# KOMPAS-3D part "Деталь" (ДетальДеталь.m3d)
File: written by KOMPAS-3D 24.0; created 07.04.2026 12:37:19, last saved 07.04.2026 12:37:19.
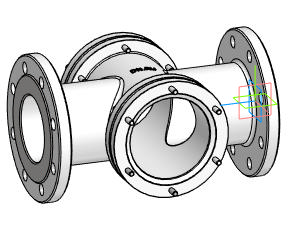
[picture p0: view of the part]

Document properties: Автор: Main; Полное имя файла: D:\DN.ru Аутсерс\Стекло смотровое DN.ru\Исходники\Стекло смотровое DN.ru SG2-34G-F тип В ГОСТ 21836-2021 Ду100 Ру16, углеродистая сталь, фланцевое\ДетальДеталь.m3d

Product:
- Body: Твердое тело1  | qty 1
- Part/product: Деталь
    additional columns: Типовые

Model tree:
1. Твердое тело1  (labels: Твердое тело1)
